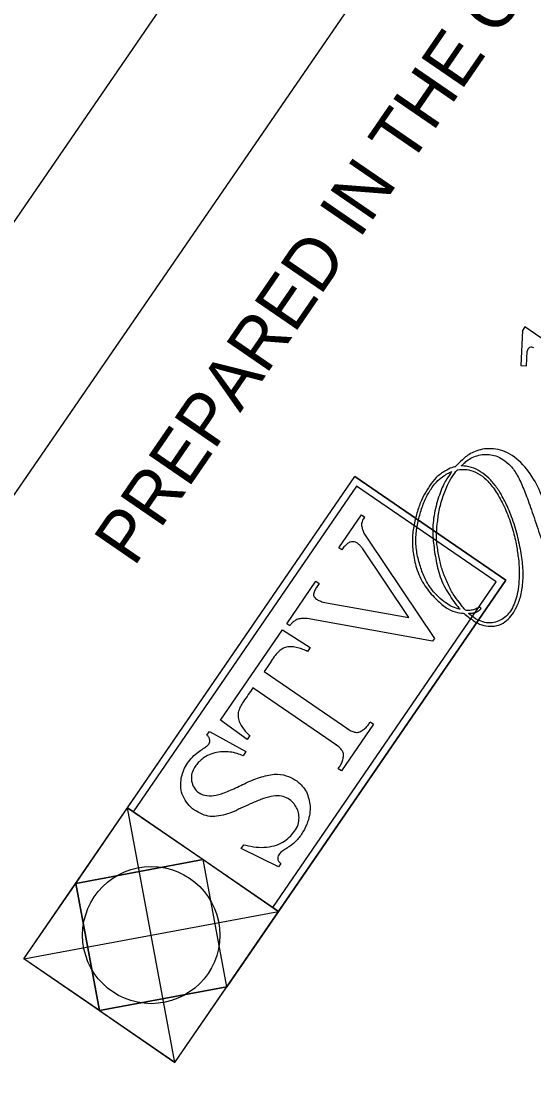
# Model space of a CAD drawing. Extents: x 1638787 to 1643250, y 391480 to 396306.
# Drawn here: x 1642054.7 to 1642181.9, y 393768.9 to 394029.8 of the extents above; entities that cross this region are included whole.
import ezdxf

# ---------------------------------------------------------------- set-up
doc = ezdxf.new("R2010")
doc.units = 0
doc.layers.add('Old_Level_60', color=7, linetype='Continuous')
doc.layers.add('UC Title Plan Sheet 34 CELL', color=7, linetype='Continuous')

msp = doc.modelspace()

# ---------------------------------------------------------------- linework, layer by layer
at = {"layer": 'Old_Level_60'}
for p, q in [((1642179.12, 393952.96), (1642178.67, 393944.23)), ((1642179.7, 393953.82), (1642179.12, 393952.96)), ((1642195.08, 393943.27), (1642179.7, 393953.82)), ((1642180.08, 393944.18), (1642180.27, 393947.81)), ((1642178.67, 393944.23), (1642180.08, 393944.18)), ((1642055.39, 393796.96), (1642137.49, 393916.69)), ((1642174.97, 393890.98), (1642137.49, 393916.69)), ((1642172.59, 393890.54), (1642137.93, 393914.31)), ((1642133.57, 393899.03), (1642139.16, 393907.17)), ((1642139.16, 393907.17), (1642139.94, 393906.63)), ((1642140.87, 393900.86), (1642157.24, 393876.48)), ((1642134.3, 393898.52), (1642133.57, 393899.03)), ((1642150.88, 393881.7), (1642139.45, 393898.72)), ((1642092.87, 393771.26), (1642174.97, 393890.98)), ((1642120.62, 393880.15), (1642127.86, 393890.7)), ((1642127.86, 393890.7), (1642128.64, 393890.17)), ((1642129.58, 393885.54), (1642150.88, 393881.7)), ((1642121.39, 393879.63), (1642120.62, 393880.15)), ((1642156.8, 393875.83), (1642125.71, 393881.44)), ((1642104.21, 393856.21), (1642119.58, 393878.63)), ((1642119.58, 393878.63), (1642126.43, 393874.26)), ((1642126.43, 393874.26), (1642125.76, 393873.28)), ((1642157.24, 393876.48), (1642156.8, 393875.83)), ((1642114.99, 393868.28), (1642136, 393853.87)), ((1642133.21, 393849.81), (1642112.2, 393864.22)), ((1642110.75, 393851.39), (1642104.21, 393856.21)), ((1642100.81, 393852.46), (1642101.43, 393853.37)), ((1642101.43, 393853.37), (1642110.47, 393848.43)), ((1642142.11, 393855.22), (1642134.16, 393843.63)), ((1642141.32, 393855.76), (1642142.11, 393855.22)), ((1642111.42, 393852.37), (1642110.75, 393851.39)), ((1642110.47, 393848.43), (1642109.76, 393847.39)), ((1642134.16, 393843.63), (1642133.37, 393844.17)), ((1642092.87, 393771.26), (1642081.09, 393834.44)), ((1642118.57, 393808.74), (1642081.09, 393834.44)), ((1642082.5, 393833.48), (1642081.09, 393834.44)), ((1642109.31, 393824.34), (1642109.95, 393825.26)), ((1642118.53, 393819.78), (1642109.31, 393824.34)), ((1642068.24, 393815.7), (1642099.83, 393821.59)), ((1642105.72, 393790), (1642099.83, 393821.59)), ((1642119.13, 393820.66), (1642118.53, 393819.78)), ((1642074.13, 393784.11), (1642068.24, 393815.7)), ((1642118.57, 393808.74), (1642117.16, 393809.71)), ((1642055.39, 393796.96), (1642118.57, 393808.74)), ((1642074.13, 393784.11), (1642105.72, 393790))]:
    msp.add_line(p, q, dxfattribs=at)
for points in [[(1642081.09, 393834.44), (1642137.49, 393916.69), (1642174.97, 393890.98), (1642118.57, 393808.74)], [(1642137.93, 393914.31), (1642082.5, 393833.48)], [(1642117.16, 393809.71), (1642172.59, 393890.54)], [(1642164.6, 393882.73), (1642164.6, 393882.72), (1642164.6, 393882.72)], [(1642092.87, 393771.26), (1642055.39, 393796.96), (1642081.09, 393834.44)]]:
    msp.add_lwpolyline(points, dxfattribs=at)
for points in [[(1642068.24, 393815.7), (1642081.09, 393834.44), (1642099.83, 393821.59)], [(1642105.72, 393790), (1642099.83, 393821.59), (1642118.57, 393808.74)], [(1642074.13, 393784.11), (1642055.39, 393796.96), (1642068.24, 393815.7)], [(1642074.13, 393784.11), (1642092.87, 393771.26), (1642105.72, 393790)]]:
    msp.add_lwpolyline(points, close=True, dxfattribs=at)
msp.add_circle((1642086.98, 393802.85), 17.02, dxfattribs=at)
msp.add_arc((1642181.34, 393947.75), 1.07, 55.5597, 177.0865, dxfattribs=at)
for points, degree in [([(1642190.57, 393917.76), (1642191.16, 393916.64), (1642193.2, 393912.81), (1642195.95, 393906.66), (1642198.78, 393899.96), (1642200.9, 393894.11), (1642201.97, 393889.4), (1642202.51, 393885.56), (1642202.36, 393883), (1642202.02, 393880.8), (1642201.12, 393879.2), (1642200.01, 393878.02), (1642198.64, 393877.6), (1642197.45, 393877.76), (1642196.76, 393878.31), (1642196.59, 393879.04), (1642197, 393879.69), (1642197.51, 393880.51), (1642197.85, 393881.76), (1642196.85, 393882.88), (1642195.33, 393882.7), (1642194.52, 393881.34), (1642194.7, 393879.73), (1642195.28, 393878.09), (1642196.77, 393877.2), (1642198.31, 393876.75), (1642199.89, 393877.06), (1642201.33, 393878.15), (1642202.28, 393879.67), (1642203.1, 393881.54), (1642203.65, 393884.04), (1642203.78, 393887.1), (1642203.69, 393890.86), (1642202.94, 393895.63), (1642201.71, 393900.65), (1642199.82, 393906.07), (1642197.65, 393911.4), (1642194.76, 393918.07), (1642192, 393924.12), (1642189.73, 393929.2), (1642188.58, 393932.19), (1642187.65, 393934.08), (1642187.26, 393935.09), (1642186.45, 393935.79), (1642185.97, 393934.85), (1642185.52, 393934.1), (1642185.43, 393932.93), (1642185.67, 393931.43), (1642186.56, 393929.05), (1642187.67, 393925.07), (1642189.21, 393919.16), (1642191.08, 393912.01), (1642192.41, 393904.84), (1642193.2, 393899.6), (1642193.07, 393896.55), (1642192.97, 393895.21), (1642192.29, 393894.12), (1642191.11, 393894.47), (1642190.22, 393895.44), (1642188.69, 393897.83), (1642187.72, 393900.84), (1642186.42, 393904.91), (1642184.94, 393909.32), (1642182.75, 393914.86), (1642179.4, 393919.9), (1642174.81, 393923.3), (1642170.06, 393923.88), (1642166.33, 393922.67), (1642164.09, 393920.89), (1642162.91, 393919.64), (1642162.5, 393919.16)], 3), ([(1642163.89, 393919.32), (1642163.91, 393919.33), (1642164.19, 393919.61), (1642164.73, 393920.14), (1642165.87, 393921.05), (1642167.34, 393921.76), (1642169.13, 393922.25), (1642170.81, 393922.19), (1642172.5, 393921.89), (1642174.2, 393921.01), (1642176.2, 393919.49), (1642177.92, 393916.98), (1642179.4, 393913.64), (1642180.84, 393909.89), (1642182.63, 393904.5), (1642184.46, 393899.02), (1642187.31, 393894.81), (1642189.59, 393893.11), (1642191.3, 393892.68), (1642192.62, 393893.13), (1642193.25, 393893.96), (1642193.86, 393895.26), (1642193.99, 393897.11), (1642193.98, 393899.45), (1642193.48, 393902.89), (1642192.88, 393907.2), (1642191.71, 393912.51), (1642190.97, 393915.92), (1642190.57, 393917.76)], 3), ([(1642162.5, 393919.16), (1642162.5, 393919.16), (1642161.65, 393918.97), (1642159.9, 393918.18), (1642157.56, 393916.49), (1642156.08, 393914.47), (1642154.72, 393912.32), (1642153.64, 393910.04), (1642152.64, 393906.85), (1642151.87, 393903.5), (1642151.69, 393899.98), (1642152.07, 393896.59), (1642153.19, 393892.31), (1642155.38, 393888.59), (1642158.23, 393885.59), (1642160.62, 393883.67), (1642163.04, 393882.85), (1642164.36, 393882.73), (1642164.6, 393882.72)], 3), ([(1642162.91, 393918.33), (1642162.94, 393918.33), (1642163.37, 393918.41), (1642164.73, 393918.54), (1642166.81, 393918.15), (1642169.21, 393916.89), (1642171.25, 393914.79), (1642173.37, 393911.75), (1642175.26, 393907.8), (1642176.84, 393903.32), (1642177.64, 393899.4), (1642178.11, 393896.25), (1642178.33, 393893.47), (1642178.25, 393890.71), (1642177.97, 393888.07), (1642177.36, 393885.96), (1642176.64, 393884.05), (1642175.57, 393882.53), (1642174.4, 393881.32), (1642172.81, 393880.67), (1642171.13, 393880.21), (1642169.27, 393880.53), (1642167.44, 393881.32), (1642166.28, 393882.18), (1642165.7, 393882.72)], 3), ([(1642164.6, 393882.72), (1642165.45, 393881.94), (1642166.82, 393880.96), (1642168.98, 393879.69), (1642171.05, 393879.43), (1642173.31, 393879.67), (1642175.27, 393880.86), (1642176.56, 393882.4), (1642177.68, 393884.27), (1642178.77, 393886.99), (1642179.31, 393890.87), (1642179.22, 393894.92), (1642178.51, 393899.18), (1642177.44, 393903.84), (1642175.79, 393908.43), (1642174.06, 393911.9), (1642172.49, 393914.37), (1642170.81, 393916.3), (1642168.75, 393917.98), (1642166.47, 393919.06), (1642164.71, 393919.33), (1642163.89, 393919.32)], 3), ([(1642163.59, 393883.74), (1642162.95, 393883.9), (1642161.71, 393884.26), (1642160.08, 393885.27), (1642158.25, 393886.73), (1642156.29, 393888.88), (1642154.68, 393891.59), (1642153.6, 393894.78), (1642152.73, 393898.11), (1642152.53, 393901.76), (1642153.08, 393905.17), (1642153.86, 393908.26), (1642155.08, 393911.44), (1642156.58, 393913.98), (1642158.13, 393915.83), (1642159.65, 393916.94), (1642160.72, 393917.6), (1642161.46, 393917.9), (1642161.53, 393917.93)], 3), ([(1642161.53, 393917.93), (1642161.5, 393917.89), (1642160.5, 393916.5), (1642159.01, 393913.84), (1642157.54, 393909.34), (1642156.68, 393904.61), (1642156.95, 393900.18), (1642157.61, 393895.8), (1642158.67, 393891.19), (1642161.05, 393886.95), (1642162.88, 393884.53), (1642163.59, 393883.74)], 3), ([(1642164.95, 393883.49), (1642164.9, 393883.54), (1642164.54, 393883.96), (1642163.48, 393885.38), (1642161.84, 393887.35), (1642160.47, 393890.35), (1642159.15, 393893.28), (1642158.43, 393896.26), (1642157.95, 393899.16), (1642157.63, 393901.84), (1642157.96, 393904.86), (1642158.32, 393908.21), (1642159.29, 393911.65), (1642160.72, 393915.1), (1642161.93, 393917.23), (1642162.82, 393918.23), (1642162.91, 393918.33)], 3), ([(1642139.94, 393906.63), (1642139.88, 393906.55), (1642139.65, 393906.22), (1642139.34, 393905.77), (1642139.25, 393905.21), (1642139.11, 393904.62), (1642139.33, 393903.85), (1642139.59, 393902.84), (1642140.19, 393901.87), (1642140.65, 393901.2), (1642140.87, 393900.86)], 3), ([(1642139.45, 393898.72), (1642139.29, 393898.94), (1642138.95, 393899.4), (1642138.35, 393900.03), (1642137.68, 393900.42), (1642137.01, 393900.55), (1642136.38, 393900.49), (1642135.71, 393900.07), (1642134.97, 393899.46), (1642134.53, 393898.86), (1642134.3, 393898.52)], 3), ([(1642128.64, 393890.17), (1642128.4, 393889.84), (1642127.94, 393889.18), (1642127.47, 393888.22), (1642127.09, 393887.2), (1642127.73, 393886.41), (1642128.55, 393885.86), (1642129.21, 393885.66), (1642129.58, 393885.54)], 3), ([(1642164.6, 393882.72), (1642164.6, 393882.72), (1642164.6, 393882.72), (1642164.6, 393882.73)], 2), ([(1642168.74, 393883.77), (1642168.76, 393883.8), (1642168.81, 393883.88), (1642168.8, 393884.07), (1642168.62, 393884.17), (1642168.48, 393884.19), (1642167.98, 393884.08), (1642166.95, 393883.53), (1642165.74, 393883.42), (1642164.99, 393883.49), (1642164.95, 393883.49)], 3), ([(1642165.7, 393882.72), (1642165.78, 393882.73), (1642166.43, 393882.77), (1642167.34, 393882.88), (1642168.25, 393883.35), (1642168.59, 393883.64), (1642168.74, 393883.77)], 3), ([(1642125.71, 393881.44), (1642125.28, 393881.46), (1642124.47, 393881.49), (1642123.32, 393881.3), (1642122.46, 393880.83), (1642121.81, 393880.27), (1642121.52, 393879.85), (1642121.39, 393879.63)], 3), ([(1642125.76, 393873.28), (1642125.45, 393873.43), (1642124.64, 393873.81), (1642123.33, 393874.23), (1642121.9, 393874.47), (1642120.53, 393874.39), (1642119.32, 393873.91), (1642118.39, 393873.05), (1642117.56, 393872.1), (1642116.5, 393870.45), (1642115.61, 393869.17), (1642114.99, 393868.28)], 3), ([(1642112.2, 393864.22), (1642111.59, 393863.32), (1642110.73, 393862.03), (1642109.57, 393860.44), (1642108.98, 393859.33), (1642108.52, 393858.15), (1642108.5, 393856.85), (1642108.92, 393855.54), (1642109.66, 393854.29), (1642110.52, 393853.23), (1642111.17, 393852.61), (1642111.42, 393852.37)], 3), ([(1642135.56, 393854.17), (1642135.93, 393853.92), (1642136.51, 393853.51), (1642137.45, 393853.24), (1642138.3, 393853.1), (1642139.21, 393853.55), (1642140.12, 393854.19), (1642140.82, 393855.01), (1642141.18, 393855.56), (1642141.32, 393855.76)], 3), ([(1642109.95, 393825.26), (1642110.64, 393825.11), (1642112.33, 393824.75), (1642114.96, 393824.53), (1642117.57, 393824.98), (1642119.74, 393825.82), (1642121.29, 393827.11), (1642122.54, 393828.61), (1642123.55, 393830.24), (1642123.7, 393832.06), (1642123.55, 393833.59), (1642122.89, 393834.76), (1642121.98, 393836.07), (1642120.56, 393837.01), (1642118.9, 393837.49), (1642116.69, 393837.36), (1642114.22, 393836.57), (1642111.45, 393835.37), (1642109.22, 393834.36), (1642107.03, 393833.27), (1642104.83, 393832.57), (1642102.66, 393832.24), (1642100.56, 393832.38), (1642098.65, 393833.29), (1642096.75, 393834.46), (1642095.35, 393836.36), (1642094.39, 393838.32), (1642094.25, 393840.43), (1642094.49, 393842.1), (1642094.98, 393843.87), (1642095.91, 393845.5), (1642097.18, 393847.12), (1642098.63, 393848.37), (1642099.99, 393849.17), (1642100.87, 393849.85), (1642101.47, 393850.41), (1642101.55, 393851.18), (1642101.41, 393851.97), (1642101.01, 393852.3), (1642100.81, 393852.46)], 3), ([(1642109.76, 393847.39), (1642109.32, 393847.57), (1642108.31, 393847.98), (1642106.58, 393848.34), (1642104.65, 393848.41), (1642102.73, 393848.12), (1642100.84, 393847.48), (1642099.57, 393846.53), (1642098.61, 393845.71), (1642097.9, 393844.78), (1642097.13, 393843.48), (1642096.84, 393841.83), (1642097.14, 393840.23), (1642098.03, 393838.71), (1642099.68, 393837.57), (1642101.92, 393837.3), (1642104.26, 393837.85), (1642107.45, 393839.07), (1642110.95, 393840.94), (1642114.86, 393842.4), (1642118.42, 393843.02), (1642121.18, 393842.27), (1642123.18, 393841.13), (1642124.51, 393839.91), (1642125.55, 393838.42), (1642126.12, 393836.69), (1642126.45, 393834.89), (1642126.36, 393833.07), (1642125.91, 393831.04), (1642124.7, 393828.43), (1642123.05, 393826.18), (1642121.41, 393824.92), (1642120.55, 393824.35), (1642119.62, 393823.81), (1642118.68, 393823.04), (1642118.27, 393821.95), (1642118.55, 393821.14), (1642118.92, 393820.82), (1642119.13, 393820.66)], 3), ([(1642133.37, 393844.17), (1642133.51, 393844.37), (1642133.89, 393844.91), (1642134.4, 393845.85), (1642134.67, 393846.94), (1642134.77, 393847.94), (1642134.33, 393848.69), (1642133.74, 393849.46), (1642133.15, 393849.86), (1642132.78, 393850.11)], 3)]:
    msp.add_open_spline(points, degree=degree, dxfattribs=at)
at = {"layer": 'UC Title Plan Sheet 34 CELL'}
for p, q in [((1640853.78, 392231.25), (1642781.17, 395041.88)), ((1641969.4, 393790.36), (1642294.19, 394263.67))]:
    msp.add_line(p, q, dxfattribs=at)

# ---------------------------------------------------------------- texts
msp.add_text('PREPARED IN THE OFFICE OF', height=12.7764, rotation=55.5455, dxfattribs=at).set_placement((1642082.7, 393894.02))

doc.saveas('drawing.dxf')
